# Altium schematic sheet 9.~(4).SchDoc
size 420 x 297 mm
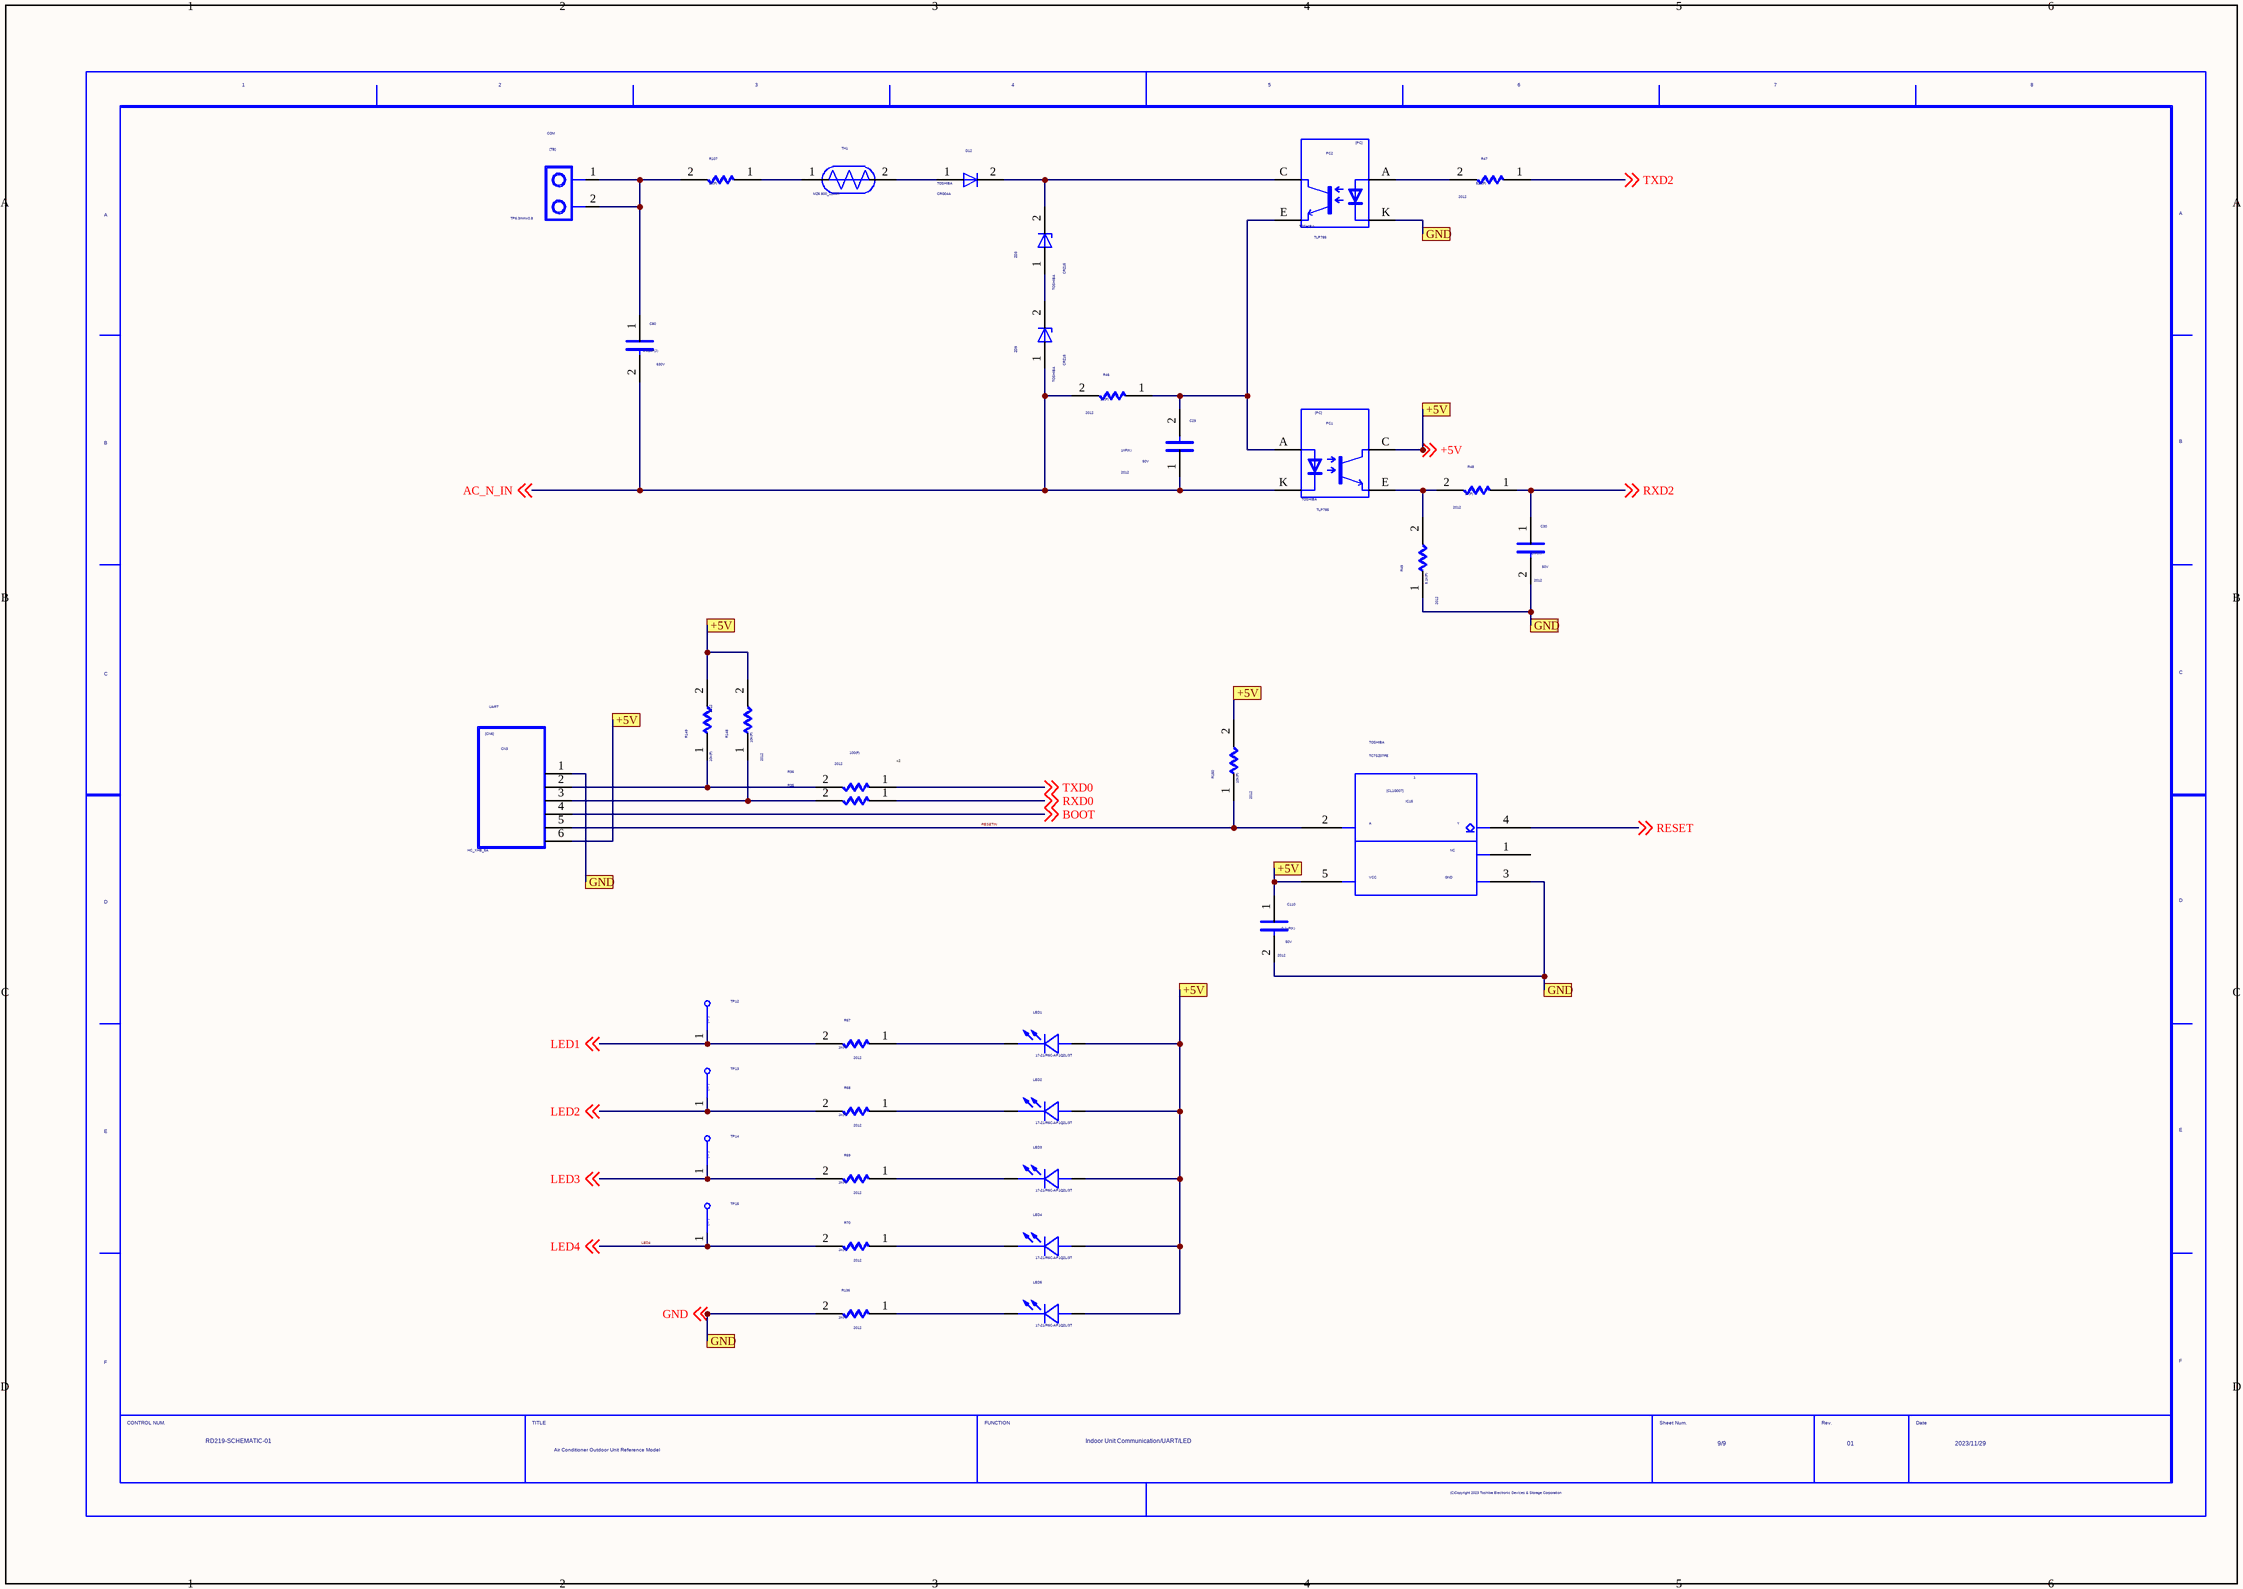
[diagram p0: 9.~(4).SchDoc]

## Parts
C29  SIZECODESMD: 2012  VAL2: 50V  VAL1: 1nF(K)  (hidden comment: C)
C30  SIZECODESMD: 2012  VAL2: 50V  VAL1: 1nF(K)  (hidden comment: C)
C80  VAL1: 0.01uF(J)  VAL2: 630V  (hidden comment: C)
C110  SIZECODESMD: 2012  VAL2: 50V  VAL1: 0.1uF(K)  (hidden comment: C)
CN3  VAL3: HC_XHB_6A  COMPCOMMENT: UART  (hidden comment: CN6)
COM  COMPCOMMENT: TP6.3mmx0.8  (hidden comment: TB2A)
D12  USERCOMPTEXT3: TOSHIBA  VAL3: CRG04A  (hidden comment: D_CUSTOM)
IC15  USERCOMPTEXT3: TOSHIBA  VAL1: TC7SZ07FE  (hidden comment: CL1G007)
LED1  VAL3: 17-21/R6C-AP1Q2L/3T  (hidden comment: LED)
LED2  VAL3: 17-21/R6C-AP1Q2L/3T  (hidden comment: LED)
LED3  VAL3: 17-21/R6C-AP1Q2L/3T  (hidden comment: LED)
LED4  VAL3: 17-21/R6C-AP1Q2L/3T  (hidden comment: LED)
LED5  VAL3: 17-21/R6C-AP1Q2L/3T  (hidden comment: LED)
PC1  USERCOMPTEXT3: TOSHIBA  (hidden comment: TLP785)
PC2  USERCOMPTEXT3: TOSHIBA  (hidden comment: TLP785)
R35  R  (value not drawn)
R36  SIZECODESMD: 2012  VAL1: 100(F)  (hidden comment: R)
R46  SIZECODESMD: 2012  VAL1: 2k(F)  (hidden comment: R)
R47  SIZECODESMD: 2012  VAL1: 510(F)  (hidden comment: R)
R48  SIZECODESMD: 2012  VAL1: 1k(F)  (hidden comment: R)
R49  SIZECODESMD: 2012  VAL1: 5.1k(F)  (hidden comment: R)
R67  SIZECODESMD: 2012  VAL1: 1k(F)  (hidden comment: R)
R68  SIZECODESMD: 2012  VAL1: 1k(F)  (hidden comment: R)
R69  SIZECODESMD: 2012  VAL1: 1k(F)  (hidden comment: R)
R70  SIZECODESMD: 2012  VAL1: 1k(F)  (hidden comment: R)
R107  VAL1: 2k(F)  (hidden comment: R)
R136  SIZECODESMD: 2012  VAL1: 1k(F)  (hidden comment: R)
R148  SIZECODESMD: 2012  VAL1: 10k(F)  (hidden comment: R)
R149  SIZECODESMD: 2012  VAL1: 10k(F)  (hidden comment: R)
R150  SIZECODESMD: 2012  VAL1: 10k(F)  (hidden comment: R)
TH1  VAL1: MZ6 800_1200R  (hidden comment: PTC)
TP12  TP  (value not drawn)
TP13  TP  (value not drawn)
TP14  TP  (value not drawn)
TP15  TP  (value not drawn)
U?  DATE: 2023/11/29  TITLE: Air Conditioner Outdoor Unit / Reference Model  SHEETNUMBER: 9/9  DRAWINGNUMBER: RD219-SCHEMATIC-01  FUNCTION: Indoor Unit Communication/UART/LED  REVISION: 01  (hidden comment: WAKU_DEF100)
ZD3  USERCOMPTEXT3: TOSHIBA  VAL1: CRZ15  (hidden comment: ZD)
ZD9  USERCOMPTEXT3: TOSHIBA  VAL1: CRZ15  (hidden comment: ZD)

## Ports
+5V, GND

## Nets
+5V: C110.1 CN3.6 IC15.5 LED1.1 LED2.1 LED3.1 LED4.1 LED5.1 PC1.C R148.2 R149.2 R150.2 ; off-sheet +5V, port +5V
AC_N_IN: C29.1 C80.2 PC1.K R46.2 ZD9.1(A) ; off-sheet AC_N_IN
BOOT: CN3.4 ; off-sheet BOOT
GND: C30.2 C110.2 CN3.1 IC15.3 PC2.K R49.1 R136.2 ; off-sheet GND, port GND
LED1: R67.2 TP12.1 ; off-sheet LED1
LED2: R68.2 TP13.1 ; off-sheet LED2
LED3: R69.2 TP14.1 ; off-sheet LED3
LED4: R70.2 TP15.1 ; off-sheet LED4
NetC29_2: C29.2 PC1.A PC2.E R46.1
NetC80_1: C80.1 COM.1 COM.2 R107.2
NetCN3_2: CN3.2 R36.2 R149.1
NetCN3_3: CN3.3 R35.2 R148.1
NetD12_1: D12.1 TH1.2
NetD12_2: D12.2 PC2.C ZD3.2(C)
NetLED1_2: LED1.2 R67.1
NetLED2_2: LED2.2 R68.1
NetLED3_2: LED3.2 R69.1
NetLED4_2: LED4.2 R70.1
NetLED5_2: LED5.2 R136.1
NetPC1_E: PC1.E R48.2 R49.2
NetPC2_A: PC2.A R47.2
NetR107_1: R107.1 TH1.1
NetZD3_1: ZD3.1(A) ZD9.2(C)
RESET: IC15.4 ; off-sheet RESET
RESETIN: CN3.5 IC15.2 R150.1
RXD0: R35.1 ; off-sheet RXD0
RXD2: C30.1 R48.1 ; off-sheet RXD2
TXD0: R36.1 ; off-sheet TXD0
TXD2: R47.1 ; off-sheet TXD2

Not connected (* = marked no-connect by the designer): IC15 1

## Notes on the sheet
- x2

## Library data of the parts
C29 C30 = C: OriginalSymbolOrigin: (2540,7620); VAL3: AC0805KRX7R9BB102
C80 = C: OriginalSymbolOrigin: (2540,7620); VAL3: CBB22_103J630V
C110 = C: OriginalSymbolOrigin: (2540,7620); VAL3: AC0805KRX7R9BB104
CN3 = CN6: OriginalSymbolOrigin: (2540,25400)
COM = TB2A: SAVEAREA0: -6249,-369,19007,18120; TIME: 11:16:32; UPDATEUSER: w20165dm; SAVECOUNT: 1; OriginalSymbolOrigin: (2540,12700); VAL3: DJ6110-6.3x0.8; COMP: TP
D12 = D_CUSTOM: SAVEAREA0: -1668,-97,14265,7829; SAVECOUNT: 4; TIME: 14:49:55; UPDATEUSER: w20165dm; UPDATETIME: 16:47:49; OriginalSymbolOrigin: (5080,5080)
IC15 = CL1G007: TIME: 15:16:30; UPDATEUSER: 19990028; UPDATETIME: 09:49:48; SAVECOUNT: 10; SAVEAREA0: -1829,-329,45053,28196; OriginalSymbolOrigin: (7620,25400)
LED1-LED5 = LED: COMP: 17_21_R6C_AP1Q2L_3T; TIME: 09:29:00; UPDATEUSER: sptcae13; UPDATETIME: 17:03:31; SAVECOUNT: 2; SAVEAREA0: -3132,-7866,12954,3909; OriginalSymbolOrigin: (0,0)
PC1 PC2 = TLP785: SAVEAREA0: -3804,-437,26060,21425; TIME: 09:38:30; UPDATEUSER: w20165dm; SAVECOUNT: 1; OriginalSymbolOrigin: (5080,17780)
R35 = R: OriginalSymbolOrigin: (5080,5080); SIZECODESMD: 2012; VAL3: AC0805FR-07100RL; VAL2: 125mW; VAL1: 100(F); COMP: AC0805FR_07100RL
R36 = R: OriginalSymbolOrigin: (5080,5080); VAL2: 125mW; VAL3: AC0805FR-07100RL; COMP: AC0805FR_07100RL
R46 = R: OriginalSymbolOrigin: (5080,5080); VAL2: 125mW; VAL3: AC0805FR-072KL; COMP: AC0805FR_072KL
R47 = R: OriginalSymbolOrigin: (5080,5080); VAL2: 125mW; VAL3: AC0805FR-07510RL; COMP: AC0805FR_07510RL
R48 = R: OriginalSymbolOrigin: (5080,5080); VAL2: 125mW; VAL3: AC0805FR-071KL; COMP: AC0805FR_071KL
R49 = R: OriginalSymbolOrigin: (5080,5080); VAL3: AC0805FR-075K1L; VAL2: 125mW; COMP: AC0805FR_075K1L
R67-R70 = R: OriginalSymbolOrigin: (5080,5080); VAL3: AC0805FR-071KL; VAL2: 125mW; COMP: AC0805FR_071KL
R107 = R: OriginalSymbolOrigin: (5080,5080); VAL3: MFR100FTE52_2K; VAL2: 1W
R136 = R: OriginalSymbolOrigin: (5080,5080); VAL3: AC0805FR_071KL; VAL2: 125mW
R148-R150 = R: OriginalSymbolOrigin: (5080,5080); VAL2: 125mW; VAL3: AC0805FR_0710KL; COMP: AC08005FR_0710KL
TH1 = PTC: TIME: 17:09:47; UPDATEUSER: w20165dm; UPDATETIME: 17:16:29; SAVECOUNT: 2; SAVEAREA0: -4525,-147,22079,13088; OriginalSymbolOrigin: (5080,7620); COMP: MZ6_800_1200R
TP12 = TP_Dup1: TIME: 16:12:21; UPDATEUSER: fukuda-y; UPDATETIME: 16:18:11; SAVECOUNT: 2; SAVEAREA0: -242,-92,12810,7836; OriginalSymbolOrigin: (0,7620); COMPCOMMENT: LED1; VAL3: ZXD
TP13 = TP_Dup1: TIME: 16:12:21; UPDATEUSER: fukuda-y; UPDATETIME: 16:18:11; SAVECOUNT: 2; SAVEAREA0: -242,-92,12810,7836; OriginalSymbolOrigin: (0,7620); COMPCOMMENT: LED2; VAL3: ZXD
TP14 = TP_Dup1: TIME: 16:12:21; UPDATEUSER: fukuda-y; UPDATETIME: 16:18:11; SAVECOUNT: 2; SAVEAREA0: -242,-92,12810,7836; OriginalSymbolOrigin: (0,7620); COMPCOMMENT: LED3; VAL3: ZXD
TP15 = TP_Dup1: TIME: 16:12:21; UPDATEUSER: fukuda-y; UPDATETIME: 16:18:11; SAVECOUNT: 2; SAVEAREA0: -242,-92,12810,7836; OriginalSymbolOrigin: (0,7620); COMPCOMMENT: LED4; VAL3: ZXD
U? = WAKU_DEF100: PLOTTIME: HH:MM; SAVEAREA0: -45080,-4508,463680,304612; TIME: 12:03:07; UPDATEUSER: sptcae13; UPDATETIME: 08:19:31; SAVECOUNT: 8; OriginalSymbolOrigin: (10160,284480)
ZD3 ZD9 = ZD: SAVEAREA0: -4071,-115,16804,10270; TIME: 09:43:08; UPDATEUSER: w20165dm; UPDATETIME: 16:32:57; SAVECOUNT: 6; OriginalSymbolOrigin: (5080,5080)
